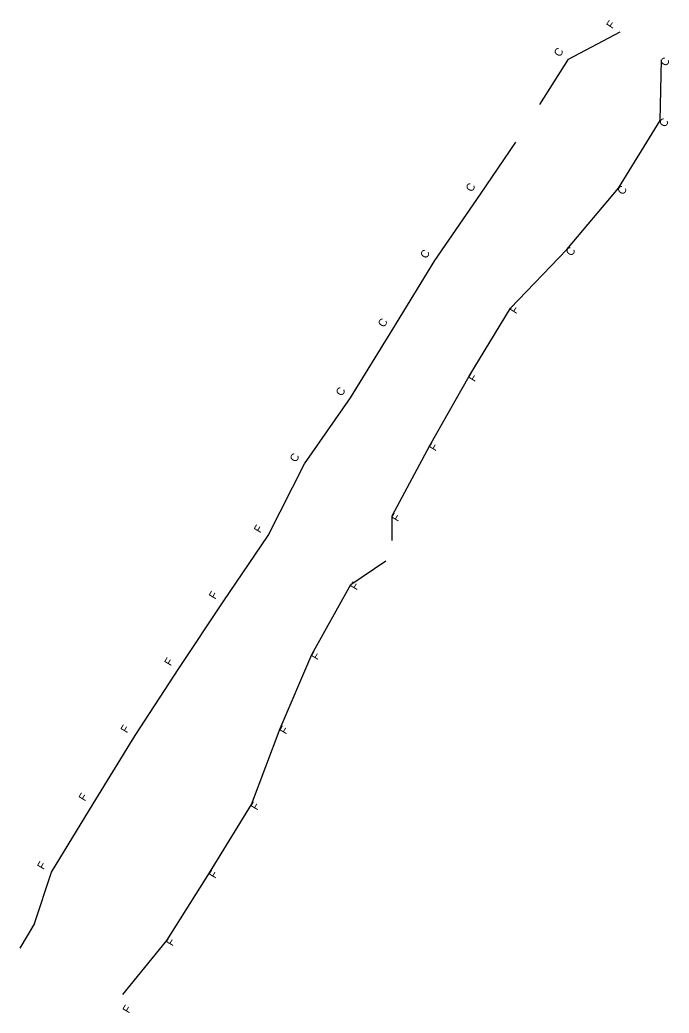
# Model space of a CAD drawing. Extents: x 2138032 to 2141442, y 405316 to 410985.
# Drawn here: x 2141036 to 2141442, y 410364 to 410985 of the extents above; entities that cross this region are included whole.
import ezdxf

# ---------------------------------------------------------------- set-up
doc = ezdxf.new("R2010")
doc.units = 0
for name, color, linetype in [('Prop Retaining Wall', 7, 'Continuous'), ('Prop SBG', 7, 'Continuous'), ('Scratch_Level_6', 7, 'Continuous'), ('Scratch_Level_7', 7, 'Continuous')]:
    doc.layers.add(name, color=color, linetype=linetype)

msp = doc.modelspace()

# ---------------------------------------------------------------- linework, layer by layer
at = {"layer": 'Prop Retaining Wall'}
for p, q in [((2141361.18, 410931.91), (2141378.97, 410960.23)), ((2141436.37, 410921.79), (2141437.08, 410959.88)), ((2141410.3, 410879.53), (2141436.37, 410921.79)), ((2141324.02, 410875.9), (2141346.26, 410908.35)), ((2141295.64, 410834.3), (2141324.02, 410875.9)), ((2141378.11, 410841.23), (2141410.3, 410879.53)), ((2141269.29, 410791.41), (2141295.64, 410834.3)), ((2141242.99, 410748.48), (2141269.29, 410791.41)), ((2141214.25, 410707.22), (2141242.99, 410748.48))]:
    msp.add_line(p, q, dxfattribs=at)
at = {"layer": 'Prop SBG'}
for p, q in [((2141378.97, 410960.23), (2141411.43, 410977.3)), ((2141342.92, 410804.65), (2141378.11, 410841.23)), ((2141191.58, 410662.53), (2141214.25, 410707.22))]:
    msp.add_line(p, q, dxfattribs=at)
at = {"layer": 'Scratch_Level_6'}
for p, q in [((2141316.97, 410762.17), (2141342.92, 410804.65)), ((2141292.46, 410718.83), (2141316.97, 410762.17)), ((2141268.96, 410674.75), (2141292.46, 410718.83)), ((2141268.96, 410659.34), (2141268.96, 410674.75)), ((2141163.46, 410621.08), (2141191.58, 410662.53)), ((2141243.15, 410631.93), (2141264.95, 410646.71)), ((2141218.8, 410588.23), (2141243.15, 410631.93)), ((2141135.67, 410579.43), (2141163.46, 410621.08)), ((2141199.04, 410541.82), (2141218.8, 410588.23)), ((2141108.34, 410537.51), (2141135.67, 410579.43)), ((2141181.01, 410494.37), (2141199.04, 410541.82)), ((2141082.14, 410494.92), (2141108.34, 410537.51)), ((2141056.27, 410452.13), (2141082.14, 410494.92)), ((2141154.92, 410451.72), (2141181.01, 410494.37)), ((2141045.62, 410420.08), (2141056.27, 410452.13)), ((2141128.17, 410409.45), (2141154.92, 410451.72)), ((2141045.62, 410420.08), (2141036.43, 410404.59)), ((2141100.73, 410375.73), (2141128.17, 410409.45))]:
    msp.add_line(p, q, dxfattribs=at)

# ---------------------------------------------------------------- texts
at = {"layer": 'Scratch_Level_7'}
for s, rotation, p in [('F', 55.82255, (2141406.41, 410978.81)), ('C', 56.19096, (2141373.61, 410961.21)), ('C', 55.82255, (2141440, 410955.28)), ('C', 56.19096, (2141439.32, 410917.21)), ('C', 57.33688, (2141318.64, 410876.78)), ('C', 56.76392, (2141413.29, 410874.98)), ('C', 57.90983, (2141290.25, 410835.12)), ('C', 57.33688, (2141381.15, 410836.71)), ('F', 57.90983, (2141346.32, 410800.66)), ('C', 58.48279, (2141263.89, 410792.18)), ('F', 58.48279, (2141320.41, 410758.21)), ('C', 59.05575, (2141237.59, 410749.19)), ('F', 59.05575, (2141295.93, 410714.9)), ('C', 59.30926, (2141208.84, 410707.91)), ('F', 59.30926, (2141272.45, 410670.84)), ('F', 59.30926, (2141186.48, 410663.73)), ('F', 59.30926, (2141246.64, 410628.02)), ('F', 59.30926, (2141158.36, 410622.27)), ('F', 59.30926, (2141222.3, 410584.33)), ('F', 59.30926, (2141130.57, 410580.63)), ('F', 59.30926, (2141103.23, 410538.71)), ('F', 59.30926, (2141202.54, 410537.91)), ('F', 59.30926, (2141077.03, 410496.11)), ('F', 59.30926, (2141184.51, 410490.47)), ('F', 59.30926, (2141051.16, 410453.32)), ('F', 59.30926, (2141158.41, 410447.81)), ('F', 59.30926, (2141131.66, 410405.55)), ('F', 59.30926, (2141104.46, 410363.55))]:
    msp.add_text(s, height=5, rotation=rotation, dxfattribs=at).set_placement(p)

doc.saveas('drawing.dxf')
